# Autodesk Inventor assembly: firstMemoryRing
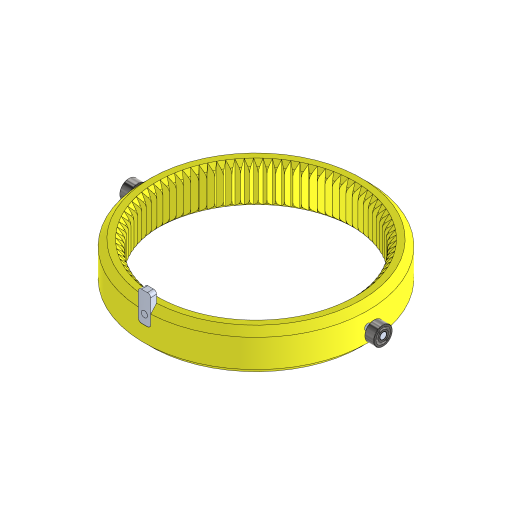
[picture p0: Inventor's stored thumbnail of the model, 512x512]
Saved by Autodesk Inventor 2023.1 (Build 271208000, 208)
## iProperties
Created: 2021-02
Part Number: firstMemoryRing
Document SubType Name: Assembly
Designer: ftrauzettel
Author: ftrauzettel
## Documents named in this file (6)
- C:\Users\Fabian\OneDrive\Delft\CPMM\Machined_Prototype\Mods\Assemblies\subAssemblies\firstMemoryRing.iam
- C:\Users\Fabian\OneDrive\Delft\CPMM\Machined_Prototype\Mods\Parts\original parts\Memory ring - first.ipt
- C:\Users\Fabian\OneDrive\Delft\CPMM\Machined_Prototype\Mods\Parts\original parts\Pin 1.ipt
- C:\Users\Fabian\OneDrive\Delft\CPMM\Machined_Prototype\Mods\Parts\original parts\Fastening pin.ipt
- C:\Users\Fabian\OneDrive\Delft\CPMM\Machined_Prototype\Mods\Parts\original parts\Bearing pin.ipt
- C:\Users\Fabian\OneDrive\Delft\CPMM\Machined_Prototype\Mods\ContentCenter\en-US\ISO 1224-1 M\ISO 1224-1 - 38 - 1 x 3 x 1.5.ipt
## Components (7 placed, 5 different names)
1. Memory ring - first:1 — Mate:3, Mate:4, Mate:5, Mate:6, Mate:7
2. Pin 1:1 — Mate:3, Mate:4
3. Fastening pin:1 — Mate:5
4. ISO 1224-1 (Metric) 38 - 1 x 3 x 1.5:1
5. Bearing pin:1 — Mate:6, Mate:7
6. ISO 1224-1 (Metric) 38 - 1 x 3 x 1.5:2
7. Bearing pin:2
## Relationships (5: Mate 5)
- Mate:3: Memory ring - first:1 ↔ Pin 1:1
- Mate:4: Memory ring - first:1 ↔ Pin 1:1
- Mate:5: Memory ring - first:1 ↔ Fastening pin:1
- Mate:6: Memory ring - first:1 ↔ Bearing pin:1
- Mate:7: Memory ring - first:1 ↔ Bearing pin:1
